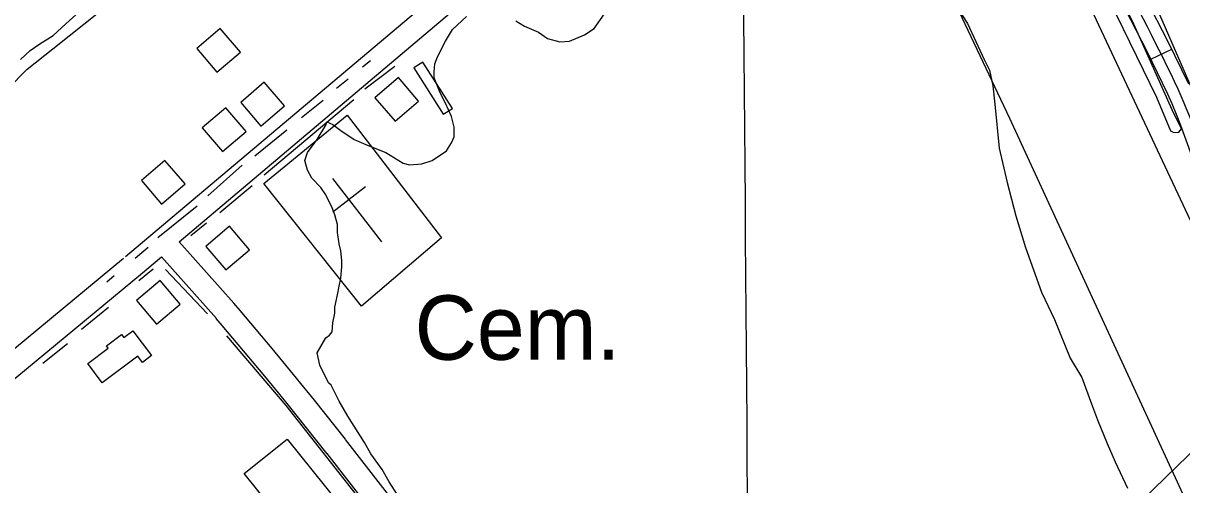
# Model space of a CAD drawing. Extents: x 3568792 to 3606828, y 529143 to 554785.
# Drawn here: x 3580651 to 3582143, y 540881 to 541476 of the extents above; entities that cross this region are included whole.
import ezdxf

# ---------------------------------------------------------------- set-up
doc = ezdxf.new("R2010")
doc.units = 0
for name, color, linetype in [('V-BLDG-OTLN', 7, 'Continuous'), ('V-GRID-MAJR', 7, 'Continuous'), ('V-ROAD-CNTR', 7, 'Continuous'), ('V-SITE-OTLN', 7, 'Continuous'), ('V-SITE-OTLN-IDEN', 7, 'Continuous'), ('V-SITE-VEGE', 7, 'Continuous'), ('V-TOPO-SHOR', 7, 'Continuous'), ('V-UTIL-LINE', 7, 'Continuous'), ('V-WETL-SWMP', 7, 'Continuous')]:
    doc.layers.add(name, color=color, linetype=linetype)

msp = doc.modelspace()

# ---------------------------------------------------------------- linework, layer by layer
at = {"layer": 'V-BLDG-OTLN'}
for points in [[(3580900.3, 541413.2), (3580930.7, 541439.2), (3580904.7, 541469.6), (3580874.3, 541443.6)], [(3581191.9, 541359), (3581203.7, 541366.5), (3581165.8, 541426.3), (3581153.9, 541418.8)], [(3580957, 541343.8), (3580987.4, 541369.8), (3580961.4, 541400.2), (3580931, 541374.2)], [(3581134.2, 541406.3), (3581103.8, 541380.3), (3581129.8, 541349.9), (3581160.2, 541375.9)], [(3580907.4, 541310.9), (3580937.8, 541336.9), (3580911.8, 541367.3), (3580881.4, 541341.3)], [(3580829, 541243.1), (3580859.4, 541269.1), (3580833.4, 541299.5), (3580803, 541273.5)], [(3580916.4, 541214.7), (3580886, 541188.7), (3580912, 541158.3), (3580942.4, 541184.3)], [(3580827.3, 541144.5), (3580796.8, 541118.7), (3580822.6, 541088.2), (3580853.1, 541114)], [(3580734, 541037.6), (3580760.3, 541057.5), (3580758, 541060.5), (3580777.5, 541075.3), (3580780.6, 541071.1), (3580791.9, 541079.7), (3580816, 541047.9), (3580804.3, 541039.1), (3580798.3, 541047.2), (3580752.5, 541012.6)], [(3580990.8, 540940.2), (3581056.1, 540859.1), (3581000.9, 540814.7), (3580935.5, 540896)]]:
    msp.add_lwpolyline(points, close=True, dxfattribs=at)
at = {"layer": 'V-GRID-MAJR'}
msp.add_spline([(3581635.7, 534620.4), (3581585.4, 540678.1), (3581535.2, 546738.9), (3581484.9, 552799.7), (3581484.9, 552802.8)], degree=3, dxfattribs=at)
at = {"layer": 'V-ROAD-CNTR'}
for p, q in [((3582103.4, 541429.8), (3582130.4, 541442.9)), ((3580529.6, 540927.3), (3580804.4, 541154.7))]:
    msp.add_line(p, q, dxfattribs=at)
for points in [[(3580782.5, 541175.5), (3581180.7, 541511.8), (3581562.4, 541838.3), (3581758.2, 542004.1)], [(3580851.8, 541194.7), (3581200.1, 541488.9), (3581581.9, 541815.4), (3581777.6, 541981.2)], [(3582152.2, 541397.9), (3582125.4, 541453.3), (3582097.4, 541507.8), (3582070.8, 541557.7)], [(3582125.2, 541384.8), (3582098.5, 541439.9), (3582070.8, 541493.9), (3582044.3, 541543.6)], [(3582124.9, 541385.4), (3582130.3, 541372.9), (3582136.2, 541358.9), (3582141.7, 541344.9), (3582147, 541330.6), (3582152.1, 541316.4), (3582156.9, 541302.1), (3582161.5, 541287.5)], [(3580922.1, 541115.6), (3580851.8, 541194.7)], [(3580513.8, 540953.2), (3580780, 541173.4)], [(3580801.9, 541152.6), (3580828.9, 541175.4)], [(3580899.7, 541095.7), (3580828.9, 541175.4)], [(3581066, 540940), (3581052.7, 540956.8), (3581039.3, 540973.6), (3581025.9, 540990.4), (3581012.4, 541007.1), (3580998.8, 541023.7), (3580985.2, 541040.3), (3580971.5, 541056.9), (3580957.7, 541073.4), (3580943.9, 541089.8), (3580930.1, 541106.2), (3580922.3, 541115.3)], [(3581042.5, 540921.4), (3581029.2, 540938.2), (3581015.9, 540954.9), (3581002.5, 540971.6), (3580989.1, 540988.2), (3580975.6, 541004.8), (3580962, 541021.3), (3580948.4, 541037.7), (3580934.7, 541054.1), (3580921, 541070.5), (3580907.2, 541086.8), (3580899.5, 541095.9)], [(3581548.1, 540321.1), (3581312.1, 540622.9), (3581066.1, 540939.9)], [(3581524.5, 540302.7), (3581288.4, 540604.5), (3581042.4, 540921.5)]]:
    msp.add_lwpolyline(points, dxfattribs=at)
for centre, radius, start, end in [((3578974.6, 539880), 3506.5, 25.5315, 28.4535), ((3581332.2, 541033.8), 882.2, 17.0225, 23.9121)]:
    msp.add_arc(centre, radius, start, end, dxfattribs=at)
at = {"layer": 'V-SITE-OTLN'}
for p, q in [((3581112.8, 541194.6), (3581049.7, 541276.2)), ((3581091.8, 541265.3), (3581049.6, 541232.7))]:
    msp.add_line(p, q, dxfattribs=at)
msp.add_lwpolyline([(3581086.4, 541111.7), (3580960.7, 541269.6), (3581068.3, 541357.6), (3581189.8, 541199.7)], close=True, dxfattribs=at)
at = {"layer": 'V-SITE-VEGE'}
for points in [[(3581842.4, 541514.5), (3581867.3, 541476), (3581888.8, 541429.6), (3581895.6, 541416), (3581900.1, 541395.6), (3581902.4, 541371.8), (3581908.1, 541315.2), (3581918.2, 541271.1), (3581929.6, 541228), (3581942, 541187.3), (3581962.4, 541129.5), (3581979.4, 541094.4), (3581999.7, 541044.6), (3582014.5, 541019.7), (3582026.9, 540985.7), (3582034.8, 540965.3), (3582047.3, 540934.8), (3582057.5, 540911), (3582073.3, 540877)], [(3581069, 540970), (3581057.7, 540989.2), (3581047.5, 541009.6), (3581044.1, 541013), (3581032.8, 541035.7), (3581029.4, 541051.5), (3581040.7, 541070.8), (3581045.3, 541074.2), (3581048.7, 541078.7), (3581049.8, 541090), (3581052.1, 541102.5), (3581052.1, 541110.4), (3581055.5, 541126.2), (3581057.7, 541137.6), (3581060, 541147.8), (3581061.1, 541162.5), (3581061.1, 541170.4), (3581060, 541182.9), (3581057.7, 541191.9), (3581055.5, 541206.6), (3581055.5, 541216.8), (3581052.1, 541229.3), (3581048.7, 541238.3), (3581040.8, 541255.3), (3581034, 541264.4), (3581022.7, 541276.8), (3581017, 541287), (3581013.6, 541299.5), (3581017, 541309.7), (3581029.5, 541326.6), (3581040.8, 541344.8), (3581041.9, 541349.3), (3581049.8, 541345.9), (3581060, 541338), (3581077, 541326.6), (3581095.1, 541318.7), (3581117.8, 541309.7), (3581140.4, 541296.1), (3581148.3, 541293.8), (3581164.2, 541294.9), (3581177.8, 541299.5), (3581195.9, 541311.9), (3581202.7, 541322.1), (3581206.1, 541330), (3581206.1, 541342.5), (3581202.7, 541356.1), (3581194.8, 541373.1), (3581188, 541386.6), (3581180, 541405.9), (3581180.1, 541413.8), (3581181.2, 541424), (3581184.6, 541433.1), (3581194.8, 541453.4), (3581203.8, 541468.2), (3581222, 541485.1)], [(3581285.4, 541479.5), (3581296.7, 541472.7), (3581314.8, 541464.7), (3581326.1, 541456.8), (3581342, 541452.3), (3581354.4, 541453.4), (3581373.7, 541461.3), (3581386.1, 541469.3), (3581399.7, 541488.5)], [(3581137, 540862.4), (3581122.2, 540885.1), (3581113.2, 540900.9), (3581098.5, 540921.3), (3581090.5, 540936), (3581069, 540970)]]:
    msp.add_lwpolyline(points, dxfattribs=at)
at = {"layer": 'V-TOPO-SHOR'}
for p, q in [((3581087.7, 541420), (3581098.2, 541428.2)), ((3581090.9, 541391.8), (3581129.7, 541420.9)), ((3581054.5, 541392.7), (3581069.5, 541404.5)), ((3580961.1, 541281.1), (3581076.8, 541378.1)), ((3581009.4, 541354.9), (3581037.2, 541377.2)), ((3580949.2, 541305.2), (3580990.2, 541338.9)), ((3580888.6, 541253.8), (3580932.8, 541293.4)), ((3580904.1, 541232.4), (3580945.6, 541267)), ((3580824.4, 541200), (3580875, 541241)), ((3580866.8, 541202.8), (3580886.8, 541219.2)), ((3580795.2, 541173.6), (3580811.6, 541187.7)), ((3580799.8, 541144.9), (3580818, 541159.9)), ((3580834, 541159), (3580888.2, 541101.6)), ((3580758.3, 541143.1), (3580767.9, 541151.3)), ((3580726, 541082.1), (3580760.6, 541110.3)), ((3580675.9, 541038.3), (3580707.8, 541063.4))]:
    msp.add_line(p, q, dxfattribs=at)
for points in [[(3581833.3, 542013.5), (3581830.6, 542017.6), (3581828.3, 542015.8), (3581827.4, 542011.2), (3581828.3, 542001.6), (3581835.2, 541979.1), (3581837, 541965.4), (3581842, 541942.9), (3581849.4, 541921.8), (3581868.2, 541887), (3581882.4, 541856.2), (3581896.6, 541815.4), (3581917.2, 541775.1), (3581945.6, 541726), (3581963.5, 541697.1), (3582000.2, 541615.1), (3582024.9, 541553.2), (3582058.8, 541487.6), (3582110.6, 541380.8), (3582128.9, 541337.7), (3582133.1, 541335.4), (3582139.3, 541335.7), (3582143.1, 541340)], [(3581833.3, 542013.5), (3581836.1, 542005.2), (3581837.9, 541996.5), (3581843, 541964.9), (3581849.4, 541942), (3581864.5, 541907.1), (3581877.8, 541884.7), (3581900.2, 541840.2), (3581921.8, 541800.3), (3581943.3, 541759.5), (3581961.7, 541727.4), (3581979.1, 541689.8), (3582009.8, 541616.9), (3582042.8, 541551.3), (3582079.4, 541479.4), (3582132.1, 541361.1), (3582143.1, 541340)], [(3580647.2, 541429.6), (3580659.6, 541441.1), (3580672, 541449.8), (3580689.4, 541460.3), (3580705.5, 541475.5), (3580775.1, 541538.7)], [(3580605.9, 541366.8), (3580655.9, 541417.3), (3580688.9, 541443.4), (3580749.9, 541492)], [(3580912.8, 541073.4), (3580989.3, 540983.6), (3581089, 540856.5)], [(3581512.5, 540318.7), (3581536.4, 540341.7), (3581737.4, 540527), (3581960, 540732.9), (3582151.7, 540919.1), (3582259.8, 541020.7)]]:
    msp.add_lwpolyline(points, dxfattribs=at)
at = {"layer": 'V-UTIL-LINE'}
for points in [[(3585128.3, 534649.8), (3583719.6, 537704.2), (3582542.5, 540395.5), (3580772.2, 544169.5), (3580472.7, 544757.3), (3580549.2, 544846), (3580609.1, 544913.1), (3580567.4, 544989.1), (3578476.1, 546727.5), (3578101.5, 547060.9), (3578033.8, 547070), (3577965.7, 547126.4), (3576392.6, 548421.7), (3576369.9, 548541.5), (3575884.2, 548880.3), (3575580.1, 549146.9), (3575181.4, 549483.6), (3575183.4, 549530.1)], [(3580613.7, 544136.9), (3580964.8, 543407.4), (3581516.1, 542211), (3581921.3, 541354.1), (3582238.9, 540665.3), (3582616.2, 539901), (3582941.5, 539167.7), (3583265.6, 538481.9), (3583288.7, 538443.2), (3583363.9, 538253.6), (3583745.1, 537485.2), (3584083.5, 536767.4), (3584210.8, 536519), (3584467.6, 535947.4)]]:
    msp.add_lwpolyline(points, dxfattribs=at)
at = {"layer": 'V-WETL-SWMP'}
msp.add_lwpolyline([(3582169.4, 541361.8), (3582067.8, 541596.2), (3581959.5, 541824.9), (3581899.3, 541934.2), (3581883.9, 541973.4), (3581882, 541991.6), (3581883.9, 542010.8), (3581895.7, 542033.6), (3581937.6, 542078.2), (3581950.4, 542091.8), (3581959.5, 542111.9), (3581957.7, 542131), (3581951.3, 542149.2), (3581932.2, 542184.8), (3581840.2, 542320.5), (3581779.2, 542408.9), (3581775.5, 542418), (3581775.5, 542424.4), (3581778.3, 542431.7), (3581787.4, 542439)], dxfattribs=at)

# ---------------------------------------------------------------- texts
at = {"layer": 'V-SITE-OTLN-IDEN'}
msp.add_text('Cem.', height=83, dxfattribs=at).set_placement((3581155, 541042.5))

doc.saveas('drawing.dxf')
